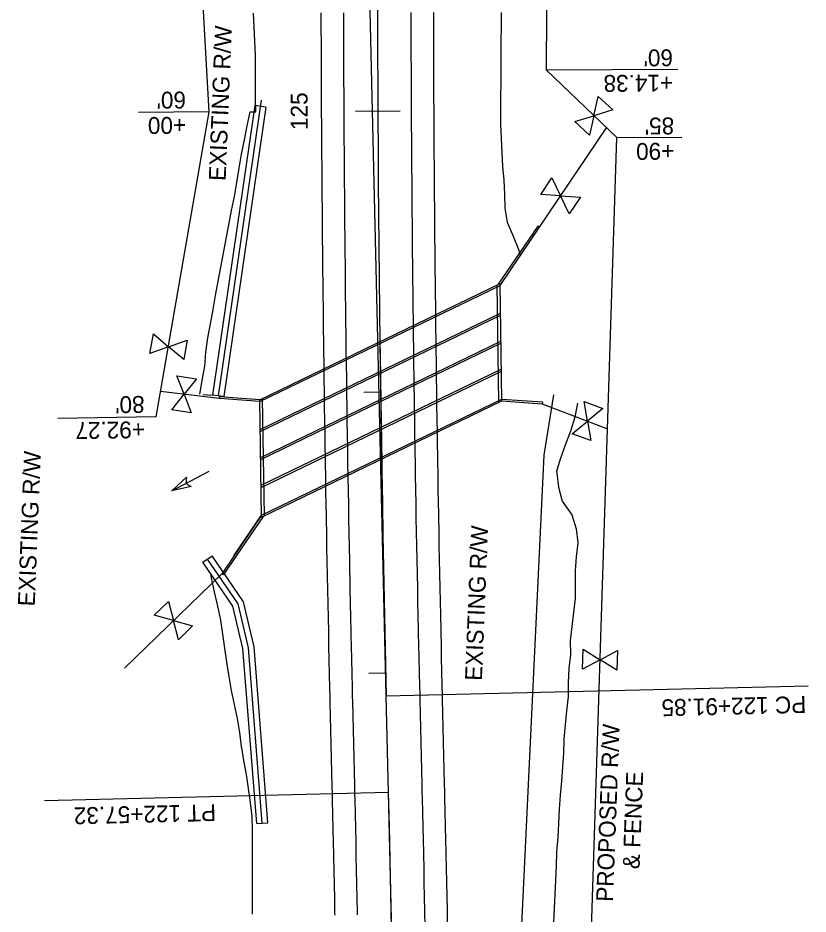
# Model space of a CAD drawing. Extents: x 634057 to 641016, y 287858 to 292331.
# Drawn here: x 634191 to 634472.2, y 291078.6 to 291397.6 of the extents above; entities that cross this region are included whole.
import ezdxf

# ---------------------------------------------------------------- set-up
doc = ezdxf.new("R2010")
doc.units = 0
for name, color, linetype in [('53', 7, 'Continuous'), ('PROPOSED SPECIAL DITCHES', 7, 'Continuous'), ('R_50 Horz Alg PC PI PT', 7, 'Continuous'), ('R_50 Horz Alg Stations', 7, 'Continuous'), ('R_50 Horz Alg Ticks', 7, 'Continuous'), ('R_Horz Alg', 7, 'Continuous'), ('R_No Plot', 7, 'Continuous'), ('R_Proposed Const Limits', 7, 'Continuous'), ('R_Proposed Road', 7, 'Continuous'), ('R_Proposed Shoulder', 7, 'Continuous'), ('R_ROW', 7, 'Continuous'), ('R_Water', 7, 'Continuous'), ('S_FENCE', 7, 'Continuous')]:
    doc.layers.add(name, color=color, linetype=linetype)

msp = doc.modelspace()

# ---------------------------------------------------------------- linework, layer by layer
for p, q in [((634319.85, 291283.81), (634320.49, 291239.22)), ((634319.87, 291282.39), (634320.47, 291240.65))]:
    msp.add_line(p, q)
at = {"layer": '53'}
for p, q in [((634379.04, 291379.12), (634402.48, 291379.26)), ((634379.04, 291379.12), (634402.48, 291379.26)), ((634402.48, 291379.26), (634425.91, 291379.41)), ((634259.11, 291364.17), (634233.95, 291364.03)), ((634259.11, 291364.17), (634233.95, 291364.03)), ((634404.17, 291355.03), (634427.36, 291355.17)), ((634404.17, 291355.03), (634427.36, 291355.17)), ((634240.21, 291255.58), (634205.26, 291255.06))]:
    msp.add_line(p, q, dxfattribs=at)
at = {"layer": 'PROPOSED SPECIAL DITCHES'}
for points in [[(634277.58, 291368.37), (634262.28, 291263.11)], [(634275.28, 291366.47), (634260.3, 291263.4)], [(634279.24, 291365.92), (634264.26, 291262.83)], [(634279.24, 291365.92), (634275.28, 291366.47)], [(634264.26, 291262.83), (634260.3, 291263.4)], [(634367.76, 291012.19), (634370.29, 291072.3), (634378.27, 291242.02), (634381.78, 291263.48)], [(634256.86, 291203.86), (634260.17, 291206.11)], [(634279.97, 291111.13), (634275.03, 291173.73), (634271.24, 291189.83), (634260.17, 291206.11)], [(634275.98, 291110.82), (634271.06, 291173.11), (634267.52, 291188.19), (634256.86, 291203.86)], [(634277.98, 291110.98), (634273.04, 291173.42), (634269.38, 291189.01), (634258.52, 291204.99)], [(634275.98, 291110.82), (634279.97, 291111.13)]]:
    msp.add_lwpolyline(points, dxfattribs=at)
at = {"layer": 'R_50 Horz Alg PC PI PT'}
for points in [[(634322.13, 291156.36), (634313.51, 291522.09)], [(634322.13, 291156.36), (634472.25, 291159.9)], [(634322.94, 291121.85), (634200.43, 291118.96)], [(634341.05, 290353.77), (634322.94, 291121.85)]]:
    msp.add_lwpolyline(points, dxfattribs=at)
at = {"layer": 'R_50 Horz Alg Ticks'}
for points in [[(634311.11, 291364.45), (634327.11, 291364.54)], [(634314.09, 291264.41), (634320.09, 291264.5)], [(634315.94, 291164.38), (634321.94, 291164.52)]]:
    msp.add_lwpolyline(points, dxfattribs=at)
at = {"layer": 'R_Horz Alg'}
msp.add_line((634322.94, 291121.85), (634322.13, 291156.36), dxfattribs=at)
for centre, start, end in [((645778.1, 291426.39), 177.693224, 181.350269), ((622866.97, 290851.82), 353.678846, 1.350269)]:
    msp.add_arc(centre, 11459.16, start, end, dxfattribs=at)
at = {"layer": 'R_Proposed Const Limits'}
for points in [[(634255.75, 291263.75), (634256.6, 291268.63), (634257.47, 291273.67), (634257.9, 291278.7), (634258.54, 291283.74), (634259.49, 291288.78), (634260.44, 291293.81), (634261.35, 291298.85), (634262.3, 291303.89), (634263.25, 291308.92), (634264.19, 291313.95), (634265.14, 291318.99), (634266.09, 291324.02), (634267.06, 291329.05), (634268.03, 291334.08), (634268.91, 291339.11), (634269.73, 291344.14), (634270.62, 291349.17), (634271.59, 291354.19), (634272.65, 291359.22), (634273.71, 291364.25), (634275.7, 291364.27), (634275.62, 291369.28), (634275.59, 291374.3), (634275.56, 291379.31), (634275.54, 291384.33), (634275.35, 291389.35), (634275.07, 291394.37), (634274.91, 291399.39)], [(634363.04, 291399.6), (634362.98, 291394.62), (634362.92, 291389.63), (634362.9, 291384.65), (634362.88, 291379.67), (634362.84, 291374.69), (634362.81, 291369.71), (634362.78, 291364.74), (634362.78, 291364.73), (634362.76, 291359.75), (634362.95, 291354.77), (634363.21, 291349.79), (634363.51, 291344.81), (634363.97, 291339.83), (634364.22, 291334.85), (634364.33, 291329.87), (634365.13, 291324.9), (634367.31, 291319.94), (634369.24, 291314.98), (634369.5, 291313.36)], [(634256.9, 291263.61), (634260.3, 291263.4)], [(634390.17, 291260.52), (634389.18, 291255.53), (634387.73, 291250.54), (634385.83, 291245.54), (634384, 291240.54), (634382.7, 291236.13), (634382.77, 291235.54), (634383.36, 291230.58), (634384.77, 291225.63), (634388.21, 291220.72), (634389.67, 291215.78), (634390.32, 291210.82), (634389.7, 291205.84), (634389.39, 291200.86), (634389.39, 291195.89), (634389.4, 291190.92), (634388.78, 291185.93), (634388.12, 291180.95), (634387.62, 291175.96), (634387.64, 291170.99), (634387.13, 291166.01), (634386.89, 291161.03), (634386.83, 291156.04), (634386.26, 291151.03), (634385.75, 291146.01), (634385.35, 291141), (634385.33, 291140.59), (634385.33, 291140.58), (634385.15, 291136), (634384.87, 291130.99), (634384.44, 291125.98), (634384.01, 291120.95), (634383.66, 291115.92), (634383.66, 291115.91), (634383.47, 291110.89), (634383.16, 291105.85), (634382.72, 291100.81), (634382.53, 291095.78), (634382.31, 291090.75), (634382.08, 291085.72), (634381.93, 291080.69), (634381.69, 291075.66)], [(634274.48, 291078.56), (634274.5, 291083.54), (634274.47, 291088.51), (634274.49, 291093.49), (634274.5, 291098.47), (634274.52, 291103.46), (634274.44, 291108.43), (634274.38, 291113.4), (634274.4, 291113.41), (634273.74, 291118.38), (634273.07, 291123.35), (634272.35, 291128.34), (634271.37, 291133.32), (634270.64, 291137.88), (634270.63, 291137.89), (634270.58, 291138.3), (634269.96, 291143.28), (634269.2, 291148.27), (634268.08, 291153.24), (634266.98, 291158.23), (634266.15, 291163.24), (634265.41, 291168.25), (634264.68, 291173.26), (634263.91, 291178.27), (634263.19, 291183.28), (634262.19, 291188.29), (634260.99, 291193.29), (634259.96, 291198.29), (634259.71, 291199.72)]]:
    msp.add_lwpolyline(points, dxfattribs=at)
at = {"layer": 'R_Proposed Road'}
for points in [[(634311.88, 291078.4), (634311.86, 291079.3), (634311.76, 291084.29), (634311.66, 291089.29), (634311.55, 291094.28), (634311.45, 291099.27), (634311.43, 291099.98), (634311.34, 291104.27), (634311.23, 291109.26), (634311.11, 291114.25), (634311, 291119.25), (634310.94, 291121.57), (634310.88, 291124.24), (634310.76, 291129.24), (634310.65, 291134.24), (634310.53, 291139.24), (634310.41, 291144.24), (634310.29, 291149.24), (634310.17, 291154.24), (634310.13, 291156.08), (634310.06, 291159.24), (634309.94, 291164.24), (634309.83, 291169.25), (634309.72, 291174.25), (634309.64, 291177.61), (634309.61, 291179.25), (634309.5, 291184.26), (634309.4, 291189.26), (634309.29, 291194.27), (634309.2, 291199.14), (634309.19, 291199.27), (634309.1, 291204.27), (634309, 291209.28), (634308.91, 291214.28), (634308.82, 291219.29), (634308.79, 291220.67), (634308.73, 291224.29), (634308.64, 291229.3), (634308.55, 291234.3), (634308.47, 291239.31), (634308.42, 291242.2), (634308.39, 291244.31), (634308.31, 291249.31), (634308.24, 291254.32), (634308.16, 291259.32), (634308.1, 291263.73), (634308.09, 291264.33), (634308.02, 291269.33), (634307.95, 291274.34), (634307.89, 291279.34), (634307.82, 291284.35), (634307.81, 291285.27), (634307.76, 291289.35), (634307.71, 291294.36), (634307.65, 291299.36), (634307.59, 291304.37), (634307.57, 291306.8), (634307.54, 291309.37), (634307.49, 291314.38), (634307.44, 291319.38), (634307.4, 291324.39), (634307.36, 291328.33), (634307.36, 291329.39), (634307.31, 291334.4), (634307.28, 291339.4), (634307.24, 291344.41), (634307.2, 291349.41), (634307.2, 291349.87), (634307.17, 291354.42), (634307.14, 291359.42), (634307.11, 291364.43), (634307.09, 291369.43), (634307.08, 291371.4), (634307.06, 291374.44), (634307.04, 291379.44), (634307.02, 291384.45), (634307, 291389.45), (634306.99, 291392.94), (634306.99, 291394.46), (634306.98, 291399.46)], [(634335.96, 291074.77), (634335.88, 291078.88), (634335.86, 291079.78), (634335.76, 291084.78), (634335.65, 291089.78), (634335.55, 291094.79), (634335.44, 291099.79), (634335.43, 291100.5), (634335.33, 291104.8), (634335.22, 291109.8), (634335.11, 291114.8), (634334.99, 291119.81), (634334.94, 291122.13), (634334.87, 291124.81), (634334.76, 291129.81), (634334.64, 291134.81), (634334.52, 291139.81), (634334.4, 291144.8), (634334.29, 291149.8), (634334.17, 291154.8), (634334.12, 291156.65), (634334.05, 291159.8), (634333.94, 291164.79), (634333.82, 291169.78), (634333.71, 291174.78), (634333.64, 291178.13), (634333.6, 291179.77), (634333.5, 291184.76), (634333.39, 291189.76), (634333.29, 291194.75), (634333.19, 291199.62), (634333.19, 291199.75), (634333.09, 291204.74), (634333, 291209.73), (634332.9, 291214.73), (634332.81, 291219.72), (634332.79, 291221.1), (634332.72, 291224.71), (634332.64, 291229.71), (634332.55, 291234.7), (634332.47, 291239.7), (634332.42, 291242.59), (634332.39, 291244.69), (634332.31, 291249.69), (634332.23, 291254.68), (634332.16, 291259.67), (634332.1, 291264.07), (634332.09, 291264.67), (634332.02, 291269.66), (634331.95, 291274.66), (634331.89, 291279.65), (634331.82, 291284.64), (634331.81, 291285.56), (634331.76, 291289.64), (634331.7, 291294.63), (634331.65, 291299.63), (634331.59, 291304.62), (634331.57, 291307.05), (634331.54, 291309.62), (634331.49, 291314.61), (634331.44, 291319.61), (634331.4, 291324.6), (634331.36, 291328.54), (634331.35, 291329.6), (634331.31, 291334.59), (634331.27, 291339.58), (634331.24, 291344.58), (634331.2, 291349.57), (634331.2, 291350.03), (634331.17, 291354.57), (634331.14, 291359.56), (634331.11, 291364.56), (634331.09, 291369.55), (634331.08, 291371.52), (634331.06, 291374.55), (634331.04, 291379.54), (634331.02, 291384.54), (634331, 291389.53), (634330.99, 291393.01), (634330.99, 291394.53), (634330.98, 291399.52)]]:
    msp.add_lwpolyline(points, dxfattribs=at)
at = {"layer": 'R_Proposed Shoulder'}
for points in [[(634303.88, 291078.24), (634303.86, 291079.14), (634303.76, 291084.13), (634303.66, 291089.12), (634303.56, 291094.11), (634303.45, 291099.1), (634303.43, 291099.81), (634303.34, 291104.09), (634303.23, 291109.08), (634303.12, 291114.07), (634303, 291119.06), (634302.95, 291121.38), (634302.88, 291124.06), (634302.77, 291129.05), (634302.65, 291134.05), (634302.53, 291139.05), (634302.41, 291144.05), (634302.29, 291149.05), (634302.18, 291154.05), (634302.13, 291155.89), (634302.06, 291159.05), (634301.94, 291164.06), (634301.83, 291169.07), (634301.72, 291174.07), (634301.65, 291177.44), (634301.61, 291179.08), (634301.5, 291184.09), (634301.4, 291189.1), (634301.3, 291194.1), (634301.2, 291198.98), (634301.2, 291199.11), (634301.1, 291204.12), (634301, 291209.13), (634300.91, 291214.14), (634300.82, 291219.14), (634300.79, 291220.53), (634300.73, 291224.15), (634300.64, 291229.16), (634300.55, 291234.17), (634300.47, 291239.17), (634300.43, 291242.07), (634300.39, 291244.18), (634300.31, 291249.19), (634300.24, 291254.2), (634300.16, 291259.21), (634300.1, 291263.62), (634300.09, 291264.22), (634300.02, 291269.22), (634299.95, 291274.23), (634299.89, 291279.24), (634299.83, 291284.25), (634299.81, 291285.17), (634299.76, 291289.26), (634299.71, 291294.27), (634299.65, 291299.27), (634299.59, 291304.28), (634299.57, 291306.72), (634299.54, 291309.29), (634299.49, 291314.3), (634299.44, 291319.31), (634299.4, 291324.32), (634299.36, 291328.27), (634299.36, 291329.32), (634299.31, 291334.33), (634299.28, 291339.34), (634299.24, 291344.35), (634299.2, 291349.36), (634299.2, 291349.81), (634299.17, 291354.37), (634299.14, 291359.38), (634299.11, 291364.39), (634299.09, 291369.39), (634299.08, 291371.36), (634299.06, 291374.4), (634299.04, 291379.41), (634299.02, 291384.42), (634299, 291389.43), (634298.99, 291392.91), (634298.99, 291394.44), (634298.98, 291399.45)], [(634343.95, 291074.93), (634343.87, 291079.04), (634343.86, 291079.93), (634343.76, 291084.94), (634343.65, 291089.95), (634343.55, 291094.96), (634343.44, 291099.97), (634343.43, 291100.68), (634343.33, 291104.97), (634343.22, 291109.98), (634343.11, 291114.99), (634342.99, 291120), (634342.94, 291122.32), (634342.87, 291125), (634342.75, 291130), (634342.64, 291135), (634342.52, 291139.99), (634342.4, 291144.99), (634342.28, 291149.99), (634342.17, 291154.99), (634342.12, 291156.84), (634342.05, 291159.98), (634341.93, 291164.97), (634341.82, 291169.96), (634341.71, 291174.95), (634341.64, 291178.3), (634341.6, 291179.94), (634341.49, 291184.93), (634341.39, 291189.92), (634341.29, 291194.91), (634341.19, 291199.77), (634341.19, 291199.9), (634341.09, 291204.89), (634340.99, 291209.88), (634340.9, 291214.87), (634340.81, 291219.87), (634340.79, 291221.24), (634340.72, 291224.86), (634340.63, 291229.85), (634340.55, 291234.84), (634340.47, 291239.83), (634340.42, 291242.72), (634340.39, 291244.82), (634340.31, 291249.81), (634340.23, 291254.8), (634340.16, 291259.79), (634340.1, 291264.19), (634340.09, 291264.78), (634340.02, 291269.77), (634339.95, 291274.76), (634339.89, 291279.75), (634339.82, 291284.74), (634339.81, 291285.66), (634339.76, 291289.73), (634339.7, 291294.73), (634339.65, 291299.72), (634339.59, 291304.71), (634339.57, 291307.13), (634339.54, 291309.7), (634339.49, 291314.69), (634339.44, 291319.68), (634339.4, 291324.67), (634339.36, 291328.61), (634339.35, 291329.66), (634339.31, 291334.65), (634339.27, 291339.65), (634339.24, 291344.64), (634339.2, 291349.63), (634339.2, 291350.08), (634339.17, 291354.62), (634339.14, 291359.61), (634339.11, 291364.6), (634339.09, 291369.59), (634339.08, 291371.56), (634339.06, 291374.58), (634339.04, 291379.57), (634339.02, 291384.57), (634339, 291389.56), (634338.99, 291393.03), (634338.99, 291394.55), (634338.98, 291399.54)]]:
    msp.add_lwpolyline(points, dxfattribs=at)
at = {"layer": 'R_ROW'}
for p, q in [((634396, 291362.84), (634397.58, 291369.73)), ((634397.58, 291369.73), (634402.76, 291364.91)), ((634389.24, 291360.77), (634396, 291362.84)), ((634396, 291362.84), (634394.42, 291355.95)), ((634402.76, 291364.91), (634396, 291362.84)), ((634394.42, 291355.95), (634389.24, 291360.77)), ((634377.11, 291334.83), (634381.09, 291340.68)), ((634381.09, 291340.68), (634384.17, 291334.31)), ((634384.17, 291334.31), (634377.11, 291334.83)), ((634387.24, 291327.95), (634384.17, 291334.31)), ((634384.17, 291334.31), (634391.22, 291333.8)), ((634391.22, 291333.8), (634387.24, 291327.95)), ((634237.99, 291278.17), (634239.24, 291285.13)), ((634239.24, 291285.13), (634244.64, 291280.57)), ((634244.64, 291280.57), (634251.29, 291282.97)), ((634251.29, 291282.97), (634250.04, 291276.01)), ((634244.64, 291280.57), (634237.99, 291278.17)), ((634250.04, 291276.01), (634244.64, 291280.57)), ((634250.13, 291263.68), (634247.54, 291270.26)), ((634247.54, 291270.26), (634254.53, 291269.21)), ((634254.53, 291269.21), (634250.13, 291263.68)), ((634245.73, 291258.15), (634250.13, 291263.68)), ((634250.13, 291263.68), (634252.72, 291257.1)), ((634393.71, 291254.13), (634392.51, 291261.1)), ((634392.51, 291261.1), (634399.14, 291258.65)), ((634252.72, 291257.1), (634245.73, 291258.15)), ((634399.14, 291258.65), (634393.71, 291254.13)), ((634388.27, 291249.61), (634393.71, 291254.13)), ((634393.71, 291254.13), (634394.91, 291247.17)), ((634394.91, 291247.17), (634388.27, 291249.61)), ((634239.54, 291184.98), (634244.59, 291189.93)), ((634244.59, 291189.93), (634246.35, 291183.09)), ((634246.35, 291183.09), (634239.54, 291184.98)), ((634248.11, 291176.24), (634246.35, 291183.09)), ((634246.35, 291183.09), (634253.16, 291181.19)), ((634253.16, 291181.19), (634248.11, 291176.24)), ((634391.97, 291165.85), (634392.23, 291172.92)), ((634392.23, 291172.92), (634398.22, 291169.16)), ((634398.22, 291169.16), (634404.47, 291172.47)), ((634404.47, 291172.47), (634404.21, 291165.41)), ((634398.22, 291169.16), (634391.97, 291165.85)), ((634404.21, 291165.41), (634398.22, 291169.16))]:
    msp.add_line(p, q, dxfattribs=at)
for points in [[(634380.33, 291604.07), (634379.04, 291379.12)], [(634240.21, 291255.58), (634259.11, 291364.17), (634249.46, 291535.15)], [(634379.04, 291379.12), (634404.17, 291355.03)], [(634385.92, 290784.2), (634404.17, 291355.03)]]:
    msp.add_lwpolyline(points, dxfattribs=at)
at = {"layer": 'R_Water'}
for p, q in [((634362.09, 291302.82), (634376.13, 291323.49)), ((634376.68, 291323.12), (634376.13, 291323.49)), ((634362.64, 291302.44), (634376.68, 291323.12)), ((634277.11, 291261.7), (634362.63, 291303.08)), ((634277.12, 291261.05), (634362.64, 291302.44)), ((634362.23, 291260.86), (634361.63, 291302.6)), ((634363.23, 291261.34), (634362.63, 291303.08)), ((634277.27, 291251.12), (634362.78, 291292.51)), ((634277.28, 291250.39), (634362.79, 291291.77)), ((634277.41, 291241.19), (634362.92, 291282.58)), ((634277.42, 291240.46), (634362.93, 291281.84)), ((634277.55, 291231.26), (634363.06, 291272.65)), ((634277.56, 291230.53), (634363.07, 291271.91)), ((634262.66, 291262.11), (634262.71, 291262.77)), ((634277.12, 291261.05), (634262.66, 291262.11)), ((634277.16, 291261.72), (634262.71, 291262.77)), ((634277.71, 291219.96), (634277.11, 291261.7)), ((634277.7, 291220.6), (634363.22, 291261.98)), ((634277.71, 291219.96), (634363.23, 291261.34)), ((634278.71, 291220.44), (634278.11, 291262.18)), ((634363.18, 291261.32), (634377.63, 291260.26)), ((634363.22, 291261.98), (634377.68, 291260.93)), ((634377.68, 291260.93), (634377.63, 291260.26)), ((634277.7, 291220.6), (634263.66, 291199.92)), ((634278.25, 291220.21), (634264.21, 291199.54)), ((634267.91, 291206.17), (634277.7, 291220.6)), ((634263.66, 291199.92), (634264.21, 291199.54))]:
    msp.add_line(p, q, dxfattribs=at)
msp.add_lwpolyline([(634245.83, 291229.35), (634259.03, 291236.25)], dxfattribs=at)
msp.add_lwpolyline([(634252.66, 291230.86), (634245.83, 291229.35), (634250.96, 291234.1), (634250.82, 291231.96)], close=True, dxfattribs=at)
at = {"layer": 'S_FENCE'}
for p, q in [((634376.68, 291323.12), (634400.53, 291358.52)), ((634262.66, 291262.11), (634241.8, 291264.71)), ((634263.66, 291199.92), (634228.93, 291166.15))]:
    msp.add_line(p, q, dxfattribs=at)
msp.add_lwpolyline([(634377.63, 291260.26), (634400.86, 291251.41)], dxfattribs=at)

# ---------------------------------------------------------------- texts
at = {"layer": '53'}
for s, rotation, p in [('EXISTING R/W', 87.6932, (634264.93, 291339.53)), ("60'  ", 180.3595, (634424.14, 291386.47)), ('+14.38 ', 180.3595, (634424.19, 291377.47)), ("60'  ", 180.3095, (634250.8, 291371.43)), ("60'  ", 180.3095, (634250.8, 291371.43)), ('+00 ', 180.3095, (634250.85, 291362.43)), ('+00 ', 180.3095, (634250.85, 291362.43)), ("85'  ", 180.3595, (634424.57, 291362.2)), ("85'  ", 180.3595, (634424.57, 291362.2)), ('+90 ', 180.3595, (634424.63, 291353.2)), ('+90 ', 180.3595, (634424.63, 291353.2)), ("80'  ", 180.8482, (634236.04, 291263.08)), ('+92.27 ', 180.8482, (634236.17, 291254.08)), ('EXISTING R/W', 87.6932, (634196.97, 291188.09)), ('EXISTING R/W', 87.6932, (634356.13, 291161.59)), ('PROPOSED R/W', 87.8162, (634402.79, 291082.91)), ('& FENCE', 87.8162, (634412.24, 291094.55))]:
    msp.add_text(s, height=6, rotation=rotation, dxfattribs=at).set_placement(p)
at = {"layer": 'R_50 Horz Alg PC PI PT'}
for s, p in [('PC 122+91.85', (634471.53, 291156.25)), ('PT 122+57.32', (634261.46, 291117.76))]:
    msp.add_text(s, height=6, rotation=181.3503, dxfattribs=at).set_placement(p)
at = {"layer": 'R_50 Horz Alg Stations'}
msp.add_text('125', height=6, rotation=90.3095, dxfattribs=at).set_placement((634294.15, 291357.76))
at = {"layer": 'R_No Plot'}
for p in [(634322.18, 291156.32), (634322.18, 291156.32), (634322.18, 291156.32), (634322.18, 291156.32), (634322.18, 291156.32), (634322.18, 291156.32), (634322.18, 291156.32), (634322.18, 291156.32), (634322.99, 291121.81), (634322.99, 291121.81), (634322.99, 291121.81), (634322.99, 291121.81), (634322.99, 291121.81), (634322.99, 291121.81), (634322.99, 291121.81), (634322.99, 291121.81)]:
    msp.add_text('+', height=0.1, rotation=91.3503, dxfattribs=at).set_placement(p)

doc.saveas('drawing.dxf')
